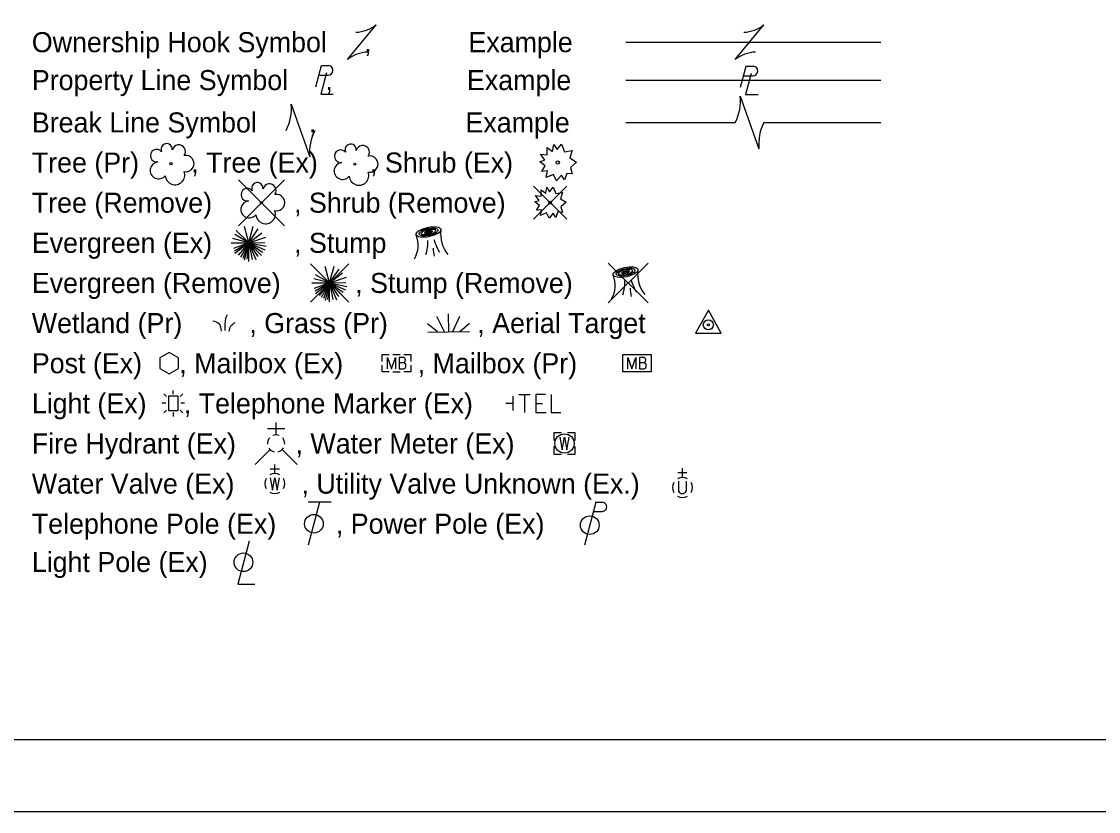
# Model space of a CAD drawing. Extents: x 0 to 34, y 0 to 22.
# Drawn here: x 8.35 to 15.87, y 0 to 5.51 of the extents above; entities that cross this region are included whole.
import ezdxf

# ---------------------------------------------------------------- set-up
doc = ezdxf.new("R2010")
doc.units = 0
for name, color, linetype in [('SH_Border', 7, 'Continuous'), ('SH_Cut_Line', 7, 'Continuous'), ('SH_Text', 7, 'Continuous')]:
    doc.layers.add(name, color=color, linetype=linetype)

msp = doc.modelspace()

# ---------------------------------------------------------------- linework, layer by layer
at = {"layer": 'SH_Border'}
msp.add_lwpolyline([(1.5, 21.5), (33.5, 21.5), (33.5, 0.5), (1.5, 0.5)], close=True, dxfattribs=at)
at = {"layer": 'SH_Cut_Line'}
msp.add_lwpolyline([(0, 0), (34, 0), (34, 22), (0, 22)], close=True, dxfattribs=at)
at = {"layer": 'SH_Text'}
for p, q in [((10.6302, 5.2474), (10.8302, 5.4874)), ((13.3384, 5.2474), (13.5384, 5.4874)), ((10.7302, 5.3674), (10.7302, 5.3674)), ((12.5729, 5.3674), (14.3552, 5.3674)), ((13.4384, 5.3674), (13.4384, 5.3674)), ((10.4305, 5.1364), (10.4953, 5.1364)), ((13.3961, 5.1323), (13.4609, 5.1323)), ((10.4705, 5.1053), (10.4705, 5.1053)), ((12.5729, 5.1028), (14.3552, 5.1028)), ((13.4362, 5.1012), (13.4362, 5.1012)), ((13.3734, 4.9916), (13.5034, 4.6234)), ((10.2378, 4.936), (10.3677, 4.5677)), ((10.3027, 4.7519), (10.3027, 4.7519)), ((12.5729, 4.8074), (13.3385, 4.8074)), ((13.4384, 4.8075), (13.4384, 4.8075)), ((13.5383, 4.8074), (14.3552, 4.8074)), ((9.8706, 4.4077), (10.1913, 4.087)), ((10.1913, 4.4077), (9.8706, 4.087)), ((11.9297, 4.3633), (12.1614, 4.1316)), ((12.1614, 4.3633), (11.9297, 4.1316)), ((10.0309, 4.2474), (10.0309, 4.2474)), ((12.0456, 4.2474), (12.0456, 4.2474)), ((9.9414, 3.9672), (9.9106, 4.0825)), ((9.9414, 3.9672), (9.9729, 4.0847)), ((9.9414, 3.9672), (10.0078, 4.0643)), ((9.9414, 3.9672), (9.8311, 3.9968)), ((9.9414, 3.9672), (9.8438, 4.0246)), ((9.9414, 3.9672), (9.8542, 4.0544)), ((9.9414, 3.9672), (10.0329, 4.0373)), ((9.9414, 3.9672), (10.0599, 4.0074)), ((9.8181, 3.9672), (9.9414, 3.9672)), ((9.9414, 3.9672), (9.8342, 3.9282)), ((9.9414, 3.9672), (9.8419, 3.9102)), ((9.9414, 3.9672), (9.8438, 3.8923)), ((9.9414, 3.9672), (9.8678, 3.8805)), ((9.9414, 3.9672), (9.8835, 3.8668)), ((9.9414, 3.9672), (9.8998, 3.8587)), ((9.9414, 3.9672), (9.9099, 3.8458)), ((9.9414, 3.9672), (9.9279, 3.8524)), ((9.9414, 3.9672), (10.0542, 3.9695)), ((9.9414, 3.8362), (9.9414, 3.9672)), ((9.9414, 3.9672), (9.9645, 3.8513)), ((9.9414, 3.9672), (9.9898, 3.8505)), ((9.9414, 3.9672), (10.0049, 3.8724)), ((9.9414, 3.9672), (10.0312, 3.8792)), ((9.9414, 3.9672), (10.037, 3.9033)), ((9.9414, 3.9672), (10.0531, 3.9187)), ((9.9414, 3.9672), (10.0622, 3.9432)), ((11.2151, 3.9674), (11.2151, 3.9674)), ((10.3718, 3.821), (10.6391, 3.5538)), ((10.6391, 3.821), (10.3718, 3.5538)), ((10.5055, 3.6874), (10.4182, 3.7746)), ((10.5055, 3.6874), (10.4746, 3.8028)), ((10.5055, 3.6874), (10.5369, 3.8049)), ((10.5055, 3.6874), (10.5718, 3.7845)), ((12.4516, 3.8265), (12.7297, 3.5484)), ((12.7297, 3.8265), (12.4516, 3.5484)), ((10.3821, 3.6874), (10.5055, 3.6874)), ((10.5055, 3.6874), (10.3951, 3.717)), ((10.5055, 3.6874), (10.3982, 3.6484)), ((10.5055, 3.6874), (10.4059, 3.6304)), ((10.5055, 3.6874), (10.4078, 3.7448)), ((10.5055, 3.6874), (10.4078, 3.6125)), ((10.5055, 3.6874), (10.4318, 3.6008)), ((10.5055, 3.6874), (10.4475, 3.587)), ((10.5055, 3.6874), (10.4638, 3.5789)), ((10.5055, 3.6874), (10.4739, 3.566)), ((10.5055, 3.6874), (10.4919, 3.5726)), ((10.5055, 3.6874), (10.5969, 3.7575)), ((10.5055, 3.6874), (10.6239, 3.7276)), ((10.5055, 3.6874), (10.6182, 3.6897)), ((10.5055, 3.5564), (10.5055, 3.6874)), ((10.5055, 3.6874), (10.5285, 3.5715)), ((10.5055, 3.6874), (10.5538, 3.5707)), ((10.5055, 3.6874), (10.5689, 3.5926)), ((10.5055, 3.6874), (10.5952, 3.5994)), ((10.5055, 3.6874), (10.601, 3.6235)), ((10.5055, 3.6874), (10.6171, 3.6389)), ((10.5055, 3.6874), (10.6262, 3.6635)), ((10.5055, 3.6874), (10.5055, 3.6874)), ((12.5907, 3.6874), (12.5907, 3.6874)), ((12.5907, 3.6874), (12.5907, 3.6874)), ((11.3371, 3.3474), (11.3352, 3.4729)), ((11.2584, 3.3463), (11.1901, 3.4034)), ((11.3071, 3.347), (11.255, 3.4531)), ((11.367, 3.3479), (11.416, 3.4554)), ((11.4158, 3.3486), (11.4823, 3.4077)), ((11.1909, 3.3452), (11.4832, 3.3496)), ((10.9482, 3.1885), (10.9983, 3.1885)), ((10.9738, 3.1274), (10.9738, 3.1274)), ((12.6519, 3.1274), (12.6519, 3.1274)), ((10.9482, 3.0663), (10.9983, 3.0663)), ((9.4142, 2.9114), (9.4142, 2.938)), ((9.3659, 2.8958), (9.3474, 2.9146)), ((9.4808, 2.9146), (9.4622, 2.8958)), ((11.7868, 2.7974), (11.7868, 2.8974)), ((9.362, 2.8478), (9.3354, 2.8478)), ((9.3659, 2.799), (9.3474, 2.7803)), ((9.4142, 2.8474), (9.4142, 2.8474)), ((9.4142, 2.7834), (9.4142, 2.7568)), ((9.4808, 2.7803), (9.4622, 2.799)), ((9.4929, 2.8478), (9.4662, 2.8478)), ((11.7868, 2.8474), (11.7371, 2.8474)), ((10.1322, 2.6276), (10.1322, 2.7136)), ((10.1922, 2.6706), (10.0722, 2.6706)), ((10.1323, 2.5674), (10.1323, 2.5674)), ((10.1323, 2.5674), (10.1323, 2.5674)), ((12.1458, 2.5674), (12.1458, 2.5674)), ((10.0899, 2.525), (9.9859, 2.4211)), ((10.1745, 2.525), (10.2785, 2.4211)), ((10.1231, 2.3574), (10.1231, 2.421)), ((10.1549, 2.3893), (10.0913, 2.3893)), ((13.001, 2.3628), (12.9374, 2.3628)), ((12.9693, 2.331), (12.9693, 2.3945)), ((10.1231, 2.2874), (10.1231, 2.2874)), ((12.9421, 2.3041), (12.9421, 2.2352)), ((12.9693, 2.261), (12.9693, 2.261)), ((12.9964, 2.3041), (12.9964, 2.2352)), ((10.4361, 2.1574), (10.3558, 1.8574)), ((10.5161, 2.1574), (10.3561, 2.1574)), ((12.3651, 2.1574), (12.2848, 1.8574)), ((12.3651, 2.1574), (12.4076, 2.1574)), ((12.348, 2.0937), (12.4076, 2.0937))]:
    msp.add_line(p, q, dxfattribs=at)
for points in [[(10.4095, 5.0568), (10.4485, 5.2051), (10.5002, 5.205)], [(13.3751, 5.0528), (13.4142, 5.201), (13.4658, 5.2009)], [(10.4839, 5.1533), (10.4443, 5.0054), (10.5316, 5.0054)], [(13.4495, 5.1492), (13.4099, 5.0013), (13.4973, 5.0013)], [(12.0943, 4.6179), (12.1245, 4.6547), (12.1453, 4.602), (12.1999, 4.611), (12.183, 4.5604), (12.2302, 4.5307), (12.1874, 4.4939), (12.1999, 4.4483), (12.1622, 4.4517), (12.146, 4.406), (12.1245, 4.4406), (12.0906, 4.3998), (12.0692, 4.4441), (12.0182, 4.4226), (12.0278, 4.4697), (11.9872, 4.4655), (12.0109, 4.505), (11.9725, 4.5334), (12.0094, 4.5466), (11.979, 4.5868), (12.0256, 4.5813), (12.0241, 4.6332), (12.0618, 4.6048), (12.0721, 4.654), (12.0943, 4.6179)], [(12.042, 4.3243), (12.0677, 4.3556), (12.0853, 4.3108), (12.1317, 4.3185), (12.1173, 4.2755), (12.1575, 4.2502), (12.1211, 4.2189), (12.1317, 4.1801), (12.0997, 4.183), (12.0859, 4.1442), (12.0677, 4.1736), (12.0388, 4.1389), (12.0206, 4.1766), (11.9773, 4.1583), (11.9854, 4.1983), (11.9509, 4.1948), (11.9711, 4.2284), (11.9384, 4.2525), (11.9698, 4.2637), (11.944, 4.2979), (11.9836, 4.2932), (11.9823, 4.3373), (12.0143, 4.3132), (12.0231, 4.355), (12.042, 4.3243)], [(9.3209, 3.0899), (9.3859, 3.0524), (9.4508, 3.0899), (9.4508, 3.1649), (9.3859, 3.2024), (9.3209, 3.1649), (9.3209, 3.0899)], [(10.8738, 3.14), (10.8738, 3.1885), (10.9223, 3.1885)], [(10.909, 3.0874), (10.909, 3.1674), (10.938, 3.0874), (10.9657, 3.1674), (10.9657, 3.0874)], [(11.0249, 3.1309), (11.028, 3.134), (11.0299, 3.1359), (11.0312, 3.1378), (11.0318, 3.1391), (11.0331, 3.1416), (11.0337, 3.1435), (11.035, 3.1479), (11.035, 3.1498), (11.035, 3.1523), (11.0343, 3.1561), (11.0331, 3.1592), (11.0312, 3.1617), (11.028, 3.1643), (11.0255, 3.1655), (11.0243, 3.1662), (11.0211, 3.1674), (10.9903, 3.1674), (10.9903, 3.0874), (11.0249, 3.0874), (11.0293, 3.0899), (11.0331, 3.0931), (11.0362, 3.0981), (11.0381, 3.1038), (11.0388, 3.1095), (11.0388, 3.1133), (11.0375, 3.117), (11.035, 3.1227), (11.0318, 3.1265), (11.0249, 3.1309), (10.9903, 3.1309)], [(11.0241, 3.1885), (11.0738, 3.1885), (11.0738, 3.14)], [(12.5871, 3.0874), (12.5871, 3.1674), (12.6161, 3.0874), (12.6438, 3.1674), (12.6438, 3.0874)], [(12.703, 3.1309), (12.7062, 3.134), (12.7081, 3.1359), (12.7093, 3.1378), (12.7099, 3.1391), (12.7112, 3.1416), (12.7118, 3.1435), (12.7131, 3.1479), (12.7131, 3.1498), (12.7131, 3.1523), (12.7125, 3.1561), (12.7112, 3.1592), (12.7093, 3.1617), (12.7062, 3.1643), (12.7037, 3.1655), (12.7024, 3.1662), (12.6992, 3.1674), (12.6684, 3.1674), (12.6684, 3.0874), (12.703, 3.0874), (12.7074, 3.0899), (12.7112, 3.0931), (12.7144, 3.0981), (12.7162, 3.1038), (12.7169, 3.1095), (12.7169, 3.1133), (12.7156, 3.117), (12.7131, 3.1227), (12.7099, 3.1265), (12.703, 3.1309), (12.6684, 3.1309)], [(10.9223, 3.0663), (10.8738, 3.0663), (10.8738, 3.1148)], [(11.0738, 3.1148), (11.0738, 3.0663), (11.0241, 3.0663)], [(11.8276, 2.9095), (11.9054, 2.9095)], [(11.867, 2.9095), (11.867, 2.7845)], [(12.0126, 2.9095), (11.9447, 2.9095), (11.9447, 2.7845), (12.0176, 2.7845)], [(12.052, 2.9095), (12.052, 2.7845), (12.1199, 2.7845)], [(11.9447, 2.8475), (11.993, 2.8475)], [(12.1258, 2.6424), (12.0708, 2.6424), (12.0708, 2.5874)], [(12.2208, 2.5874), (12.2208, 2.6424), (12.1658, 2.6424)], [(12.1125, 2.6124), (12.1292, 2.5224), (12.1458, 2.6124), (12.1625, 2.5224), (12.1792, 2.6124)], [(12.0708, 2.5474), (12.0708, 2.4924), (12.1258, 2.4924)], [(12.1658, 2.4924), (12.2208, 2.4924), (12.2208, 2.5474)], [(10.0913, 2.3284), (10.1072, 2.2423), (10.1231, 2.3284), (10.1391, 2.2423), (10.1549, 2.3284)], [(9.9434, 1.8862), (9.8647, 1.5869), (9.9828, 1.5869)]]:
    msp.add_lwpolyline(points, dxfattribs=at)
for points in [[(13.0601, 3.3374), (13.2401, 3.3374), (13.1501, 3.4984)], [(12.5519, 3.1885), (12.7519, 3.1885), (12.7519, 3.0663), (12.5519, 3.0663)], [(9.3808, 2.7974), (9.4474, 2.7974), (9.4474, 2.8974), (9.3808, 2.8974)]]:
    msp.add_lwpolyline(points, close=True, dxfattribs=at)
for centre, radius in [((9.3979, 4.5193), 0.0084), ((10.6825, 4.5159), 0.0072), ((12.0985, 4.5274), 0.0115), ((10.0309, 4.2474), 0.0072), ((12.0455, 4.2474), 0.00979), ((13.1501, 3.3953), 0.035), ((13.1501, 3.3953), 0.008), ((12.1458, 2.5674), 0.0675), ((10.396, 2.0074), 0.065), ((12.3223, 1.9974), 0.065), ((9.9041, 1.7385), 0.065)]:
    msp.add_circle(centre, radius, dxfattribs=at)
for centre, radius, start, end in [((10.6721, 5.7024), 0.2668, 273.69448, 306.33701), ((13.3803, 5.7024), 0.2668, 273.69448, 306.33701), ((10.7883, 5.0325), 0.2668, 93.69448, 126.33701), ((13.4965, 5.0325), 0.2668, 93.69448, 126.33701), ((10.495, 5.1709), 0.0345, 270.47098, 81.3281), ((13.4606, 5.1668), 0.0345, 270.47098, 81.3281), ((13.0414, 4.9592), 0.3335, 332.94224, 5.58476), ((9.9058, 4.9035), 0.3335, 332.94224, 5.58476), ((10.6997, 4.6002), 0.3335, 152.94224, 185.58476), ((13.8354, 4.6558), 0.3335, 152.94224, 185.58476), ((9.2987, 4.5752), 0.0441, 39.06254, 279.54124), ((9.3684, 4.6203), 0.0395, 354.0047, 205.97412), ((9.4527, 4.6042), 0.0466, 323.82996, 165.0376), ((10.5833, 4.5718), 0.0441, 39.06254, 279.54124), ((10.653, 4.6169), 0.0395, 354.0047, 205.97412), ((10.7373, 4.6007), 0.0466, 323.82996, 165.0376), ((9.3123, 4.4729), 0.0592, 96.17219, 320.57371), ((9.5017, 4.5204), 0.0574, 259.14531, 101.45961), ((10.5969, 4.4694), 0.0592, 96.17219, 320.57371), ((10.7863, 4.5169), 0.0574, 259.14531, 101.45961), ((9.4263, 4.4412), 0.0685, 184.94757, 19.45715), ((10.7109, 4.4377), 0.0685, 184.94757, 19.45715), ((10.0014, 4.3484), 0.0395, 354.0047, 205.97412), ((10.0857, 4.3323), 0.0466, 323.82996, 165.0376), ((9.9317, 4.3033), 0.0441, 39.06254, 279.54124), ((10.1348, 4.2485), 0.0574, 259.14531, 101.45961), ((9.9453, 4.2009), 0.0592, 96.17219, 320.57371), ((10.0593, 4.1692), 0.0685, 184.94757, 19.45715), ((10.9235, 3.9501), 0.2001, 331.53375, 20.92689), ((11.5405, 4.0702), 0.316, 194.9653, 212.12159), ((11.4954, 4.0245), 0.2146, 171.41061, 219.91939), ((10.9392, 3.9687), 0.2527, 340.79377, 3.54808), ((11.4104, 3.9274), 0.1819, 178.79264, 197.12241), ((12.871, 3.7445), 0.2146, 171.41061, 219.91939), ((12.2991, 3.6701), 0.2001, 331.53375, 20.92689), ((12.3148, 3.6887), 0.2527, 340.79377, 3.54808), ((12.9161, 3.7902), 0.316, 194.9653, 212.12159), ((12.7859, 3.6474), 0.1819, 178.79264, 197.12241), ((10.1323, 2.5674), 0.06, 140.02099, 184.06293), ((10.1323, 2.5674), 0.06, 68.13946, 112.03798), ((10.1323, 2.5674), 0.06, 356.01648, 39.98885), ((10.1323, 2.5674), 0.06, 211.87877, 255.84793), ((10.1323, 2.5674), 0.06, 283.82389, 329.90967), ((10.1231, 2.2875), 0.07, 60.01836, 120.01574), ((12.9693, 2.2611), 0.07, 60.01836, 120.01574), ((10.1231, 2.2875), 0.07, 150.01836, 209.98164), ((10.1231, 2.2875), 0.07, 330.01836, 29.98164), ((12.9693, 2.2611), 0.07, 150.01836, 209.98164), ((12.9693, 2.2611), 0.07, 330.01836, 29.98164), ((10.1231, 2.2875), 0.07, 239.98426, 299.98164), ((12.9693, 2.2611), 0.07, 239.98426, 299.98164), ((12.9692, 2.248), 0.03, 205.19243, 334.80757), ((12.4083, 2.1255), 0.0319, 268.8767, 91.1233)]:
    msp.add_arc(centre, radius, start, end, dxfattribs=at)
for centre, major_axis in [((11.1964, 4.043), (0.0868, 0.0187)), ((11.1964, 4.043), (0.0651, 0.0141)), ((11.1964, 4.043), (0.0488, 0.0105)), ((11.1964, 4.043), (0.0275, 0.0059)), ((11.1964, 4.043), (0.0154, 0.0033)), ((12.5719, 3.763), (0.0868, 0.0187)), ((12.5719, 3.763), (0.0651, 0.0141)), ((12.5719, 3.763), (0.0488, 0.0105)), ((12.5719, 3.763), (0.0275, 0.0059)), ((12.5719, 3.763), (0.0154, 0.0033))]:
    msp.add_ellipse(centre, major_axis=major_axis, ratio=0.36865, dxfattribs=at)
for points in [[(9.7775, 3.356), (9.7775, 3.4033), (9.7834, 3.4477), (9.7923, 3.4685)], [(9.6902, 3.423), (9.7316, 3.4053), (9.7493, 3.352)], [(9.8053, 3.3488), (9.8171, 3.3872), (9.8466, 3.411)]]:
    msp.add_spline(points, degree=3, dxfattribs=at)

# ---------------------------------------------------------------- texts
for s, p in [('Ownership Hook Symbol     ,             Example', (8.4266, 5.2974)), ('Property Line Symbol     ,                  Example', (8.4266, 5.0328)), ('Break Line Symbol       ,                    Example', (8.4266, 4.7374)), ('Tree (Pr)       , Tree (Ex)       , Shrub (Ex)', (8.4266, 4.4574)), ('Tree (Remove)           , Shrub (Remove)', (8.4266, 4.1774)), ('Evergreen (Ex)           , Stump ', (8.4266, 3.8974)), ('Evergreen (Remove)          , Stump (Remove)', (8.4266, 3.6174)), ('Wetland (Pr)         , Grass (Pr)            , Aerial Target    ', (8.4266, 3.3374)), ('Post (Ex)     , Mailbox (Ex)          , Mailbox (Pr)', (8.4266, 3.0574)), ('Light (Ex)     , Telephone Marker (Ex)     ', (8.4266, 2.7774)), ('Fire Hydrant (Ex)        , Water Meter (Ex)', (8.4266, 2.4974)), ('Water Valve (Ex)         , Utility Valve Unknown (Ex.)', (8.4266, 2.2174)), ('Telephone Pole (Ex)        , Power Pole (Ex)', (8.4266, 1.9374)), ('Light Pole (Ex)     ', (8.4266, 1.6704))]:
    msp.add_text(s, height=0.14, dxfattribs=at).set_placement(p)

doc.saveas('drawing.dxf')
